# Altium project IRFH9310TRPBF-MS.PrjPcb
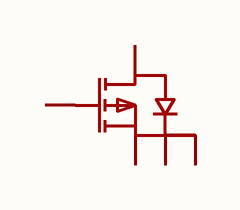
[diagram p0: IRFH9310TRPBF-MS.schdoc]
1 sheet, 1 parts. Net scope: global (net labels, ports and power ports of the same name join across sheets).

## Sheet IRFH9310TRPBF-MS.schdoc
size 127 x 101 mm

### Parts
Q?  irfh9310trpbf-ms  [TDSON-8_L5.9-W5.2-P1.27-BL-1]  (value not drawn)

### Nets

Not connected (* = marked no-connect by the designer): Q? 1(S) 2(S) 3(S) 4(G) 5(D)

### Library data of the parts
Q? = irfh9310trpbf-ms: 数量:1个P沟道;漏源电压(Vdss):30V;连续漏极电流(Id):90A;导通电阻(RDS(on)):3.5mΩ@10V;耗散功率(Pd):60W;阈值电压(Vgs(th)):1.6V;; Manufacturer: MSKSEMI(美森科); AddInBom: yes; ModelId: 6d3ef2b64d5a4f2dbd2ee02e0c7053d2; ModelTransform: 205.511,242.1255,0,0,0,0,0,42.913,0; Number: 1个P沟道; Drain to Source Voltage: 30V; Current - Continuous Drain(Id): 90A; Pd - Power Dissipation: 60W; Gate Threshold Voltage (Vgs(th)): 1.6V; Gate Charge(Qg): 146nC; Input Capacitance(Ciss): 5.07nF; Reverse Transfer Capacitance (Crss@Vds): 580pF; Configuration: 独立式; Type: P沟道; Output Capacitance(Coss): 695pF; Vgs: ±20V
